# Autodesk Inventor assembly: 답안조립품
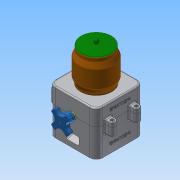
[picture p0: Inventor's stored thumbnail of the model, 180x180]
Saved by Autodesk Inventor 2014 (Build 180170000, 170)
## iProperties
Created: 2018-01
Part Number: 답안조립품
Document SubType Name: Assembly
Designer: 601-24
Author: 601-24
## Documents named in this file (9)
- C:\Users\601-24\Desktop\480108V1013\답안조립품.iam
- C:\Users\601-24\Desktop\480108V1013\본체.ipt
- C:\Users\601-24\Desktop\480108V1013\본체커버.ipt
- C:\Users\601-24\Desktop\480108V1013\볼트 M3x12.ipt
- C:\Users\601-24\Desktop\480108V1013\볼트 M4x12.ipt
- C:\Users\601-24\Desktop\480108V1013\용기.ipt
- C:\Users\601-24\Desktop\480108V1013\용기캡.ipt
- C:\Users\601-24\Desktop\480108V1013\핸들.ipt
- C:\Users\601-24\Desktop\480108V1013\핸들축.ipt
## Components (2 placed, 2 different names)
1. 핸들:1
2. 핸들축:1 — 플러쉬:1
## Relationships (1: Flush 1)
- 플러쉬:1 [Flush]: 핸들축:1
